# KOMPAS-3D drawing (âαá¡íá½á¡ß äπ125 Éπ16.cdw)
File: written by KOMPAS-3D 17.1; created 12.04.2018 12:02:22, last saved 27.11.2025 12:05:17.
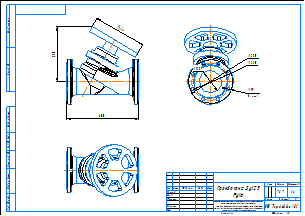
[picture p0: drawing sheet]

Sheet 1: A3, landscape

Title block, sheet 1: name: Гранбаланс Ду125 / Ру16; material: Сталь 20  ГОСТ 1050-88; mass: 76,7; sheets: 1; sheet format: A3; stored path: C:\Users\kka\KOMPAS_Work\!Trash\КМ125 КМ127 КМ225Ф Двухходовые клапана\КМ125Ф + PSL\KOMPAS 2D\Гранрег КМ125Ф Ду32 Ру16.cdw

Views: Спереди 1, Спереди, Проекционный вид 2, Проекционный вид 3
Referenced files in C:\Users\mipv\Desktop\КБЧ\Имеющиеся\: Гранбаланс Ду125 Ру16  серия 10.m3d
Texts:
  kka
  adl
  Рама для чертежей
  Лит-Масса-Масштаб
  Материал-Предприятие
  Масштаб
  Изм.
  Лист
  № докум.
  Подп.
  Дата
  Лит.
  Разраб.
  Пров.
  Т.контр.
  Листов
  Внимание! Данный продукт является объектом авторского права ООО «Торговый Дом АДЛ».
  Запрещается изменение, копирование, распространение
  (в том числе путем копирования на другие сайты и ресурсы в Интернете)
  или любое иное использование информации и объектов без предварительного
  согласия правообладателя (ООО «Торговый Дом АДЛ»).
  Н.контр.
  Утв.
  ООО "Торговый дом АДЛ"
  Изменение
  Номер документа
  Подпись
  Обозначение документа
  Наименование изделия
  Масса изделия по ГОСТ 2.109-73
  Порядковый номер листа
  Общее количество листов в документе
  Характер работы, выполненной лицом, подписавшим документ
  Наименование или индекс предприятия, выпускающего документ
  Инв. № подл.
  Подп. и дата
  Взам. инв. №
  Инв. № дубл.
  Инвентарный номер подлинника по ГОСТ 2.501-68
  Подпись принявшего подлинник в отдел технической документации
  Инвентарный номер подлинника, взамен которого выпущен данный подлинник
  Инвентарный номер дубликата по ГОСТ 2.502-68
  Подпись принявшего дубликат в отдел технической документации
  Справ. №
  Перв. примен.
  Обозначение документа, взамен или на основании которого выпущен данный документ
  Обозначение документа, в котором впервые записан данный документ
  Подпись лица, копировавшего чертеж
  Обозначение формата листа
  !Рама для чертежа
Dimensions and other numbers on the sheet: 400; 290; 320; 250; 210; 125; 19; 8 отв.; 1:4; 1; 76,7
